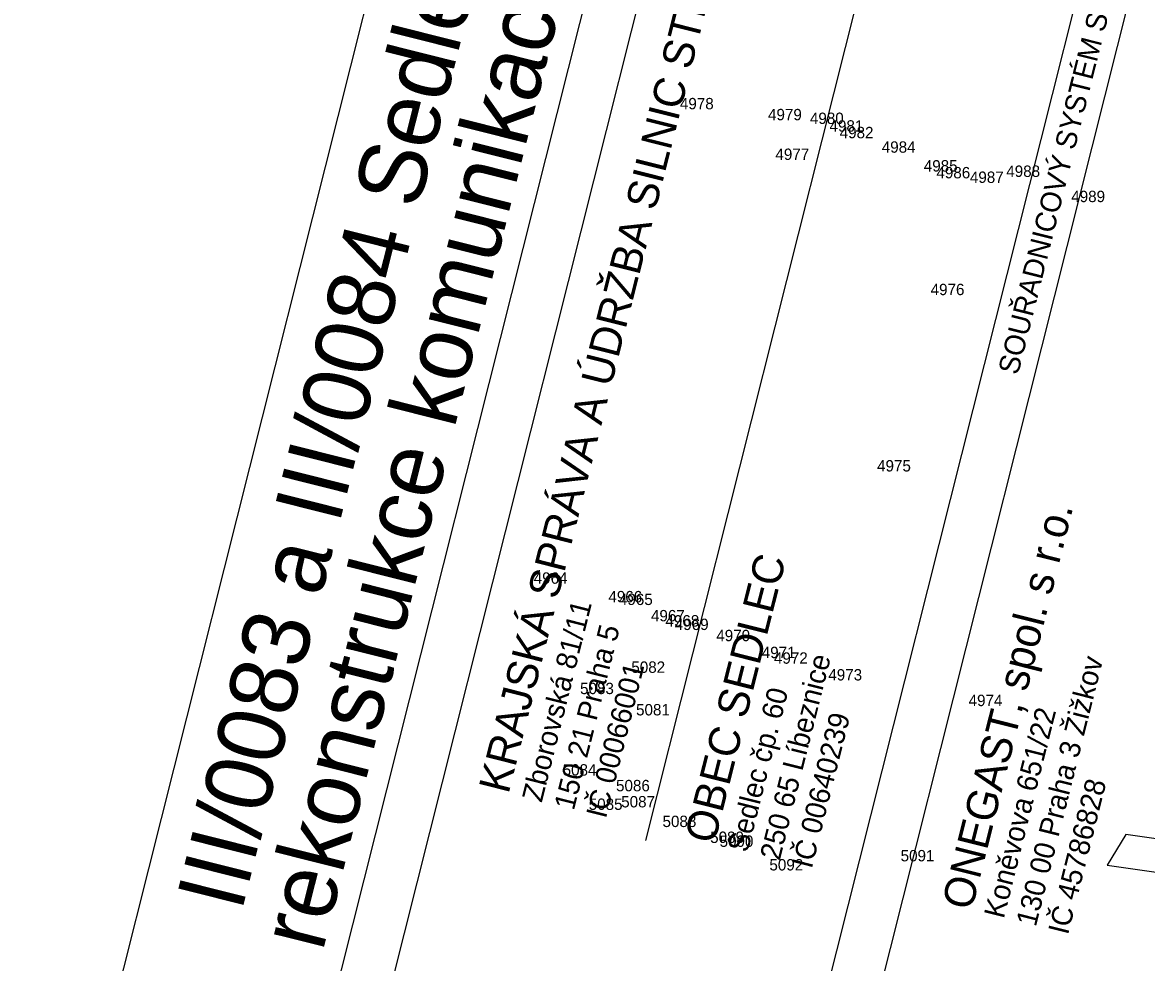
# Model space of a CAD drawing. Extents: x -740053 to -737517, y -1033516 to -1032488.
# Drawn here: x -738977.1 to -738922.7, y -1032991.8 to -1032946.3 of the extents above; entities that cross this region are included whole.
import ezdxf

# ---------------------------------------------------------------- set-up
doc = ezdxf.new("R2010")
doc.units = 0
for name, color, linetype in [('bod-cislo', 7, 'Continuous'), ('promika-rozp', 7, 'Continuous'), ('promika-rozp-text', 7, 'Continuous'), ('promika-rozp-text-firmy', 7, 'Continuous'), ('Vrstva 1', 7, 'Continuous')]:
    doc.layers.add(name, color=color, linetype=linetype)

msp = doc.modelspace()

# ---------------------------------------------------------------- linework, layer by layer
at = {"layer": 'promika-rozp'}
msp.add_lwpolyline([(-738967.114, -1033013.951), (-738945.143, -1032926.674), (-738955.083, -1032924.172), (-738977.054, -1033011.449)], close=True, dxfattribs=at)
for points in [[(-738932.779, -1032929.787), (-738942.719, -1032927.284), (-738964.69, -1033014.561), (-738954.75, -1033017.063)], [(-738932.779, -1032929.787), (-738922.839, -1032932.289), (-738944.81, -1033019.566), (-738954.75, -1033017.063)], [(-738922.506, -1033025.181), (-738942.386, -1033020.176), (-738920.415, -1032932.899), (-738900.535, -1032937.904)], [(-738946.895, -1032985.861), (-738935.525, -1032940.696)]]:
    msp.add_lwpolyline(points, dxfattribs=at)
at = {"layer": 'Vrstva 1'}
msp.add_lwpolyline([(-738924.575, -1032987.062), (-738915.214, -1032988.389), (-738914.311, -1032986.906), (-738923.672, -1032985.579)], close=True, dxfattribs=at)

# ---------------------------------------------------------------- texts
at = {"layer": 'bod-cislo'}
for s, p in [('4978', (-738945.248, -1032950.493)), ('4979', (-738940.985, -1032951.023)), ('4980', (-738938.958, -1032951.203)), ('4981', (-738938.009, -1032951.573)), ('4982', (-738937.518, -1032951.893)), ('4984', (-738935.481, -1032952.593)), ('4977', (-738940.628, -1032952.943)), ('4985', (-738933.448, -1032953.503)), ('4986', (-738932.838, -1032953.833)), ('4988', (-738929.458, -1032953.763)), ('4987', (-738931.218, -1032954.053)), ('4989', (-738926.315, -1032954.983)), ('4976', (-738933.118, -1032959.483)), ('4975', (-738935.708, -1032968.013)), ('4964', (-738952.321, -1032973.443)), ('4966', (-738948.708, -1032974.343)), ('4965', (-738948.198, -1032974.473)), ('4967', (-738946.648, -1032975.263)), ('4968', (-738945.948, -1032975.513)), ('4969', (-738945.495, -1032975.683)), ('4970', (-738943.488, -1032976.223)), ('4971', (-738941.289, -1032977.043)), ('5082', (-738947.598, -1032977.753)), ('4972', (-738940.698, -1032977.313)), ('4973', (-738938.068, -1032978.123)), ('5083', (-738950.078, -1032978.783)), ('4974', (-738931.281, -1032979.363)), ('5081', (-738947.369, -1032979.813)), ('5084', (-738950.921, -1032982.723)), ('5086', (-738948.338, -1032983.483)), ('5087', (-738948.088, -1032984.263)), ('5085', (-738949.658, -1032984.383)), ('5088', (-738946.088, -1032985.213)), ('5089', (-738943.785, -1032985.983)), ('5090', (-738943.328, -1032986.173)), ('5091', (-738934.569, -1032986.873)), ('5092', (-738940.918, -1032987.313))]:
    msp.add_text(s, height=0.55, dxfattribs=at).set_placement(p)
at = {"layer": 'promika-rozp'}
msp.add_text('SOUŘADNICOVÝ SYSTÉM S-JTSK  VÝŠKOVÝ SYSTÉM Bpv', height=1, rotation=75.8698, dxfattribs=at).set_placement((-738928.895, -1032963.383))
at = {"layer": 'promika-rozp-text'}
for s, height, p in [('ONEGAST, spol. s r.o.', 1.5, (-738931.132, -1032989.293)), ('130 00 Praha 3 Žižkov', 1, (-738928.029, -1032990.074)), ('Koněvova 651/22', 1, (-738929.58, -1032989.684)), ('IČ 45786828', 1, (-738926.477, -1032990.465))]:
    msp.add_text(s, height=height, rotation=75.8698, dxfattribs=at).set_placement(p)
at = {"layer": 'promika-rozp-text-firmy'}
for s, height, p in [('KRAJSKÁ SPRÁVA A ÚDRŽBA SILNIC STŘEDOČESKÉHO KRAJE, P.O.', 1.5, (-738953.542, -1032983.652)), ('III/0083 a III/0084 Sedlec,', 3.25, (-738966.457, -1032989.368)), ('rekonstrukce komunikací', 3.25, (-738962.537, -1032991.295)), ('OBEC SEDLEC', 1.5, (-738943.583, -1032986.078)), ('Zborovská 81/11', 1, (-738951.933, -1032984.057)), ('150 21 Praha 5', 1, (-738950.381, -1032984.447)), ('250 65 Líbeznice', 1, (-738940.422, -1032986.873)), ('IČ 00066001', 1, (-738948.83, -1032984.838)), ('Sedlec čp. 60', 1, (-738941.974, -1032986.483)), ('IČ 00640239', 1, (-738938.871, -1032987.264))]:
    msp.add_text(s, height=height, rotation=75.8698, dxfattribs=at).set_placement(p)

doc.saveas('drawing.dxf')
